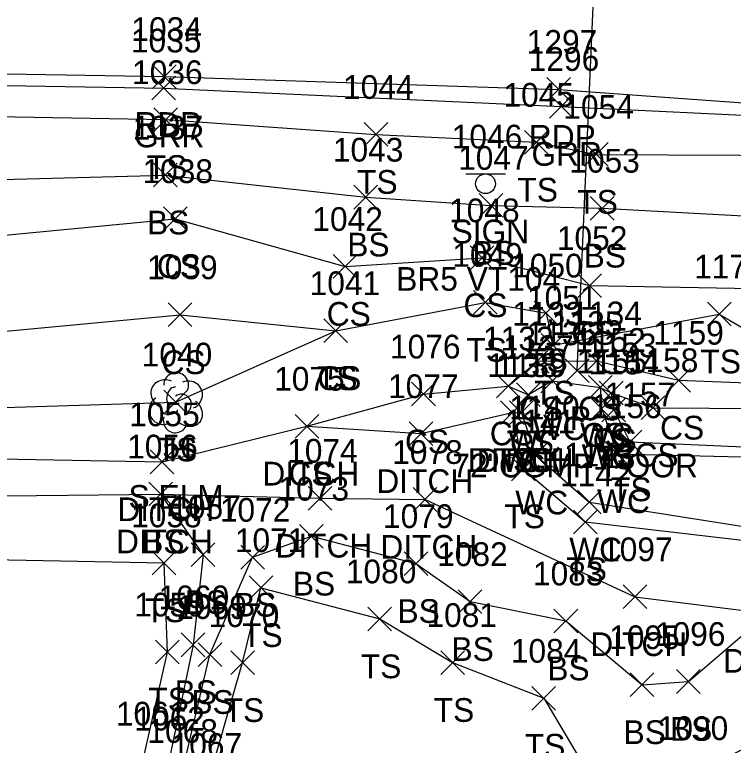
# Model space of a CAD drawing. Extents: x 1514253 to 1516033, y 782541 to 785002.
# Drawn here: x 1515259.8 to 1515320.5, y 782627.7 to 782689.3 of the extents above; entities that cross this region are included whole.
import ezdxf

# ---------------------------------------------------------------- set-up
doc = ezdxf.new("R2010")
doc.units = 0
for name, color, linetype in [('D_A', 7, 'Continuous'), ('D_C', 7, 'Continuous'), ('D_I', 7, 'Continuous'), ('D_TIC', 7, 'Continuous'), ('DCP', 7, 'Continuous'), ('DD', 7, 'Continuous'), ('L_A', 7, 'Continuous'), ('L_C', 7, 'Continuous'), ('L_I', 7, 'Continuous'), ('L_TIC', 7, 'Continuous'), ('LAWE', 7, 'Continuous'), ('LELB', 7, 'Continuous'), ('LTD', 7, 'Continuous'), ('P_A', 7, 'Continuous'), ('P_I', 7, 'Continuous'), ('P_TIC', 7, 'Continuous'), ('PET', 7, 'Continuous'), ('R_A', 7, 'Continuous'), ('R_I', 7, 'Continuous'), ('R_TIC', 7, 'Continuous'), ('RGR', 7, 'Continuous'), ('S_A', 7, 'Continuous'), ('S_C', 7, 'Continuous'), ('S_I', 7, 'Continuous'), ('SSGN', 7, 'Continuous')]:
    doc.layers.add(name, color=color, linetype=linetype)

msp = doc.modelspace()

# ---------------------------------------------------------------- linework, layer by layer
at = {"layer": 'D_TIC'}
for points in [[(1515306.297, 782658.246), (1515308.297, 782660.246)], [(1515308.297, 782658.246), (1515306.297, 782660.246)], [(1515300.839, 782654.709), (1515302.839, 782656.709)], [(1515302.839, 782654.709), (1515300.839, 782656.709)], [(1515301.59, 782654.701), (1515303.59, 782656.701)], [(1515303.59, 782654.701), (1515301.59, 782656.701)], [(1515283.508, 782653.562), (1515285.508, 782655.562)], [(1515285.508, 782653.562), (1515283.508, 782655.562)], [(1515293.121, 782652.933), (1515295.121, 782654.933)], [(1515295.121, 782652.933), (1515293.121, 782654.933)], [(1515271.278, 782650.56), (1515273.278, 782652.56)], [(1515273.278, 782650.56), (1515271.278, 782652.56)], [(1515271.163, 782647.844), (1515273.163, 782649.844)], [(1515273.163, 782647.844), (1515271.163, 782649.844)], [(1515284.608, 782647.488), (1515286.608, 782649.488)], [(1515286.608, 782647.488), (1515284.608, 782649.488)], [(1515293.464, 782647.384), (1515295.464, 782649.384)], [(1515295.464, 782647.384), (1515293.464, 782649.384)], [(1515311.17, 782639.182), (1515313.17, 782641.182)], [(1515313.17, 782639.182), (1515311.17, 782641.182)]]:
    msp.add_lwpolyline(points, dxfattribs=at)
at = {"layer": 'DCP'}
msp.add_lwpolyline([(1515307.297, 782659.246), (1515310.82, 782739.152)], dxfattribs=at)
at = {"layer": 'DD'}
for points in [[(1515199.546, 782651.884), (1515235.764, 782652.236), (1515272.278, 782651.56), (1515284.508, 782654.562), (1515294.121, 782653.933), (1515301.839, 782655.709), (1515302.59, 782655.701)], [(1515199.394, 782648.84), (1515235.483, 782648.45), (1515272.163, 782648.844), (1515285.608, 782648.488), (1515294.464, 782648.384), (1515312.17, 782640.182), (1515323.367, 782638.781), (1515329.306, 782640.309), (1515333.451, 782637.848), (1515333.036, 782633.949), (1515334.721, 782622.814), (1515328.394, 782601.12)]]:
    msp.add_lwpolyline(points, dxfattribs=at)
at = {"layer": 'L_TIC'}
for points in [[(1515271.581, 782679.406), (1515273.581, 782681.406)], [(1515273.581, 782679.406), (1515271.581, 782681.406)], [(1515289.322, 782678.158), (1515291.322, 782680.158)], [(1515291.322, 782678.158), (1515289.322, 782680.158)], [(1515302.85, 782677.499), (1515304.85, 782679.499)], [(1515304.85, 782677.499), (1515302.85, 782679.499)], [(1515307.9, 782676.477), (1515309.9, 782678.477)], [(1515309.9, 782676.477), (1515307.9, 782678.477)], [(1515271.569, 782674.732), (1515273.569, 782676.732)], [(1515273.569, 782674.732), (1515271.569, 782676.732)], [(1515288.461, 782672.873), (1515290.461, 782674.873)], [(1515290.461, 782672.873), (1515288.461, 782674.873)], [(1515299.027, 782672.178), (1515301.027, 782674.178)], [(1515301.027, 782672.178), (1515299.027, 782674.178)], [(1515308.403, 782671.939), (1515310.403, 782673.939)], [(1515310.403, 782671.939), (1515308.403, 782673.939)], [(1515272.401, 782671.059), (1515274.401, 782673.059)], [(1515274.401, 782671.059), (1515272.401, 782673.059)], [(1515298.264, 782667.757), (1515300.264, 782669.757)], [(1515300.264, 782667.757), (1515298.264, 782669.757)], [(1515286.729, 782667.029), (1515288.729, 782669.029)], [(1515288.729, 782667.029), (1515286.729, 782669.029)], [(1515307.354, 782665.42), (1515309.354, 782667.42)], [(1515309.354, 782665.42), (1515307.354, 782667.42)], [(1515298.54, 782664.004), (1515300.54, 782666.004)], [(1515300.54, 782664.004), (1515298.54, 782666.004)], [(1515272.8, 782662.957), (1515274.8, 782664.957)], [(1515274.8, 782662.957), (1515272.8, 782664.957)], [(1515303.675, 782663.101), (1515305.675, 782665.101)], [(1515305.675, 782663.101), (1515303.675, 782665.101)], [(1515318.285, 782663.015), (1515320.285, 782665.015)], [(1515320.285, 782663.015), (1515318.285, 782665.015)], [(1515285.933, 782661.615), (1515287.933, 782663.615)], [(1515287.933, 782661.615), (1515285.933, 782663.615)], [(1515285.933, 782661.615), (1515287.933, 782663.615)], [(1515287.933, 782661.615), (1515285.933, 782663.615)], [(1515304.267, 782660.39), (1515306.267, 782662.39)], [(1515306.267, 782660.39), (1515304.267, 782662.39)], [(1515302.943, 782659.043), (1515304.943, 782661.043)], [(1515304.943, 782659.043), (1515302.943, 782661.043)], [(1515307.932, 782659.064), (1515309.932, 782661.064)], [(1515309.932, 782659.064), (1515307.932, 782661.064)], [(1515304.221, 782657.389), (1515306.221, 782659.389)], [(1515306.221, 782657.389), (1515304.221, 782659.389)], [(1515304.221, 782657.389), (1515306.221, 782659.389)], [(1515306.221, 782657.389), (1515304.221, 782659.389)], [(1515314.851, 782657.437), (1515316.851, 782659.437)], [(1515316.851, 782657.437), (1515314.851, 782659.437)], [(1515300.485, 782656.951), (1515302.485, 782658.951)], [(1515302.485, 782656.951), (1515300.485, 782658.951)], [(1515300.485, 782656.951), (1515302.485, 782658.951)], [(1515302.485, 782656.951), (1515300.485, 782658.951)], [(1515308.247, 782656.829), (1515310.247, 782658.829)], [(1515310.247, 782656.829), (1515308.247, 782658.829)], [(1515308.247, 782656.829), (1515310.247, 782658.829)], [(1515310.247, 782656.829), (1515308.247, 782658.829)], [(1515293.334, 782656.273), (1515295.334, 782658.273)], [(1515295.334, 782656.273), (1515293.334, 782658.273)], [(1515302.181, 782656.217), (1515304.181, 782658.217)], [(1515304.181, 782656.217), (1515302.181, 782658.217)], [(1515302.181, 782656.217), (1515304.181, 782658.217)], [(1515304.181, 782656.217), (1515302.181, 782658.217)], [(1515309.163, 782656.372), (1515311.163, 782658.372)], [(1515311.163, 782656.372), (1515309.163, 782658.372)], [(1515309.163, 782656.372), (1515311.163, 782658.372)], [(1515311.163, 782656.372), (1515309.163, 782658.372)], [(1515272.423, 782655.598), (1515274.423, 782657.598)], [(1515274.423, 782655.598), (1515272.423, 782657.598)], [(1515300.839, 782654.709), (1515302.839, 782656.709)], [(1515302.839, 782654.709), (1515300.839, 782656.709)], [(1515308.37, 782655.024), (1515310.37, 782657.024)], [(1515310.37, 782655.024), (1515308.37, 782657.024)], [(1515309.383, 782654.934), (1515311.383, 782656.934)], [(1515311.383, 782654.934), (1515309.383, 782656.934)], [(1515312.696, 782655.121), (1515314.696, 782657.121)], [(1515314.696, 782655.121), (1515312.696, 782657.121)], [(1515301.59, 782654.701), (1515303.59, 782656.701)], [(1515303.59, 782654.701), (1515301.59, 782656.701)], [(1515283.508, 782653.562), (1515285.508, 782655.562)], [(1515285.508, 782653.562), (1515283.508, 782655.562)], [(1515310.738, 782652.239), (1515312.738, 782654.239)], [(1515312.738, 782652.239), (1515310.738, 782654.239)], [(1515302.77, 782651.127), (1515304.77, 782653.127)], [(1515304.77, 782651.127), (1515302.77, 782653.127)], [(1515309.661, 782651.237), (1515311.661, 782653.237)], [(1515311.661, 782651.237), (1515309.661, 782653.237)], [(1515301.751, 782649.961), (1515303.751, 782651.961)], [(1515303.751, 782649.961), (1515301.751, 782651.961)], [(1515271.163, 782647.844), (1515273.163, 782649.844)], [(1515273.163, 782647.844), (1515271.163, 782649.844)], [(1515307.32, 782647.165), (1515309.32, 782649.165)], [(1515309.32, 782647.165), (1515307.32, 782649.165)], [(1515306.982, 782645.496), (1515308.982, 782647.496)], [(1515308.982, 782645.496), (1515306.982, 782647.496)], [(1515283.876, 782644.286), (1515285.876, 782646.286)], [(1515285.876, 782644.286), (1515283.876, 782646.286)], [(1515274.745, 782642.731), (1515276.745, 782644.731)], [(1515276.745, 782642.731), (1515274.745, 782644.731)], [(1515278.925, 782642.508), (1515280.925, 782644.508)], [(1515280.925, 782642.508), (1515278.925, 782644.508)], [(1515271.442, 782642.038), (1515273.442, 782644.038)], [(1515273.442, 782642.038), (1515271.442, 782644.038)], [(1515292.699, 782641.978), (1515294.699, 782643.978)], [(1515294.699, 782641.978), (1515292.699, 782643.978)], [(1515279.627, 782639.948), (1515281.627, 782641.948)], [(1515281.627, 782639.948), (1515279.627, 782641.948)], [(1515297.257, 782638.773), (1515299.257, 782640.773)], [(1515299.257, 782638.773), (1515297.257, 782640.773)], [(1515289.641, 782637.315), (1515291.641, 782639.315)], [(1515291.641, 782637.315), (1515289.641, 782639.315)], [(1515305.339, 782637.14), (1515307.339, 782639.14)], [(1515307.339, 782637.14), (1515305.339, 782639.14)], [(1515273.9, 782635.131), (1515275.9, 782637.131)], [(1515275.9, 782635.131), (1515273.9, 782637.131)], [(1515271.72, 782634.52), (1515273.72, 782636.52)], [(1515273.72, 782634.52), (1515271.72, 782636.52)], [(1515275.319, 782634.308), (1515277.319, 782636.308)], [(1515277.319, 782634.308), (1515275.319, 782636.308)], [(1515278.076, 782633.626), (1515280.076, 782635.626)], [(1515280.076, 782633.626), (1515278.076, 782635.626)], [(1515295.789, 782633.635), (1515297.789, 782635.635)], [(1515297.789, 782633.635), (1515295.789, 782635.635)], [(1515315.681, 782632.039), (1515317.681, 782634.039)], [(1515317.681, 782632.039), (1515315.681, 782634.039)], [(1515311.767, 782631.766), (1515313.767, 782633.766)], [(1515313.767, 782631.766), (1515311.767, 782633.766)], [(1515303.473, 782630.621), (1515305.473, 782632.621)], [(1515305.473, 782630.621), (1515303.473, 782632.621)]]:
    msp.add_lwpolyline(points, dxfattribs=at)
at = {"layer": 'LAWE'}
for points in [[(1515305.221, 782658.389), (1515303.181, 782657.217), (1515302.59, 782655.701), (1515303.77, 782652.127), (1515308.32, 782648.165), (1515322.585, 782645.92), (1515334.724, 782645.203), (1515346.696, 782645.723), (1515355.669, 782642.743), (1515362.112, 782639.578)], [(1515305.221, 782658.389), (1515309.247, 782657.829), (1515309.37, 782656.024), (1515310.661, 782652.237), (1515328.158, 782651.8), (1515339.372, 782649.611), (1515359.133, 782646.008), (1515370.291, 782640.974), (1515378.24, 782634.81), (1515385.256, 782635.895), (1515388.599, 782640.179), (1515389.121, 782646.36), (1515386.777, 782649.906), (1515390.568, 782651.945), (1515397.927, 782652.705), (1515407.459, 782649.219), (1515414.933, 782648.068), (1515419.945, 782646.777), (1515424.071, 782644.52), (1515427.947, 782638.847), (1515430.432, 782625.437), (1515426.178, 782619.034), (1515431.378, 782612.516)]]:
    msp.add_lwpolyline(points, dxfattribs=at)
at = {"layer": 'LELB'}
for points in [[(1515198.723, 782678.684), (1515237.654, 782681.037), (1515272.581, 782680.406), (1515290.322, 782679.158), (1515303.85, 782678.499), (1515308.9, 782677.477), (1515327.05, 782677.392), (1515347.388, 782677.23), (1515355.314, 782675.991), (1515384.856, 782670.273), (1515402.641, 782668.137), (1515426.898, 782664.758), (1515431.084, 782662.879), (1515448.442, 782660.296)], [(1515199.146, 782675.609), (1515237.424, 782674.791), (1515272.569, 782675.732), (1515289.461, 782673.873), (1515300.027, 782673.178), (1515309.403, 782672.939), (1515327.016, 782671.989), (1515352.175, 782674.367), (1515355.484, 782668.368), (1515355.529, 782661.896), (1515362.199, 782656.243), (1515384.653, 782653.272), (1515398.956, 782656.377), (1515406.884, 782653.846), (1515416.301, 782653.121), (1515424.335, 782655.884), (1515430.378, 782659.607), (1515449.299, 782656.525)], [(1515199.979, 782655.093), (1515236.324, 782655.449), (1515273.423, 782656.598), (1515286.933, 782662.615), (1515299.54, 782665.004), (1515304.675, 782664.101), (1515305.267, 782661.39), (1515319.285, 782664.015), (1515324.873, 782660.753), (1515330.533, 782661.03), (1515335.531, 782663.335), (1515351.626, 782666.228), (1515352.175, 782674.367)], [(1515199.887, 782668.087), (1515237.312, 782668.583), (1515273.401, 782672.059), (1515287.729, 782668.029), (1515299.264, 782668.757), (1515308.354, 782666.42), (1515328.224, 782666.061), (1515330.533, 782661.03), (1515333.755, 782659.052), (1515343.884, 782659.192), (1515351.413, 782658.187), (1515355.484, 782668.368), (1515366.848, 782667.84), (1515384.002, 782666.142), (1515400.676, 782664.245), (1515424.648, 782661.721), (1515431.013, 782661.432), (1515448.86, 782658.438)], [(1515199.251, 782662.64), (1515236.544, 782660.479), (1515273.8, 782663.957), (1515286.933, 782662.615)], [(1515284.508, 782654.562), (1515294.334, 782657.273), (1515301.485, 782657.951), (1515303.943, 782660.043), (1515308.932, 782660.064), (1515315.851, 782658.437), (1515327.358, 782657.995), (1515341.712, 782655.566), (1515348.371, 782655.012), (1515351.413, 782658.187), (1515355.529, 782661.896), (1515364.984, 782660.684), (1515382.517, 782659.229), (1515399.983, 782660.3), (1515424.268, 782658.95)], [(1515301.485, 782657.951), (1515303.181, 782657.217)], [(1515309.247, 782657.829), (1515310.163, 782657.372), (1515313.696, 782656.121), (1515327.927, 782656.035), (1515341.024, 782653.35), (1515349.767, 782652.941), (1515361.602, 782650.791), (1515374.165, 782648.283), (1515380.971, 782647.67), (1515386.077, 782649.544)], [(1515310.163, 782657.372), (1515310.383, 782655.934), (1515311.738, 782653.239), (1515327.12, 782652.556), (1515340.38, 782650.599), (1515359.526, 782647.53), (1515371.713, 782643.995), (1515378.608, 782636.912), (1515384.051, 782637.622), (1515387.007, 782640.366), (1515387.011, 782646.011), (1515386.077, 782649.544), (1515388.534, 782653.757), (1515398.392, 782653.907), (1515407.552, 782650.359), (1515415.675, 782649.762), (1515419.247, 782648.751), (1515425.267, 782646.15), (1515433.214, 782625.745), (1515427.667, 782618.999), (1515432.728, 782613.436)], [(1515301.839, 782655.709), (1515302.751, 782650.961), (1515307.982, 782646.496), (1515322.678, 782644.788), (1515335.13, 782644.312), (1515345.143, 782643.295), (1515351.972, 782643.192)], [(1515272.163, 782648.844), (1515275.745, 782643.731), (1515274.9, 782636.131), (1515272.765, 782625.903), (1515266.399, 782619.826)], [(1515198.67, 782646.535), (1515234.653, 782643.768), (1515272.442, 782643.038), (1515272.72, 782635.52), (1515270.641, 782626.326), (1515264.311, 782620.96)], [(1515267.096, 782619.076), (1515273.864, 782624.863), (1515276.319, 782635.308), (1515279.925, 782643.508), (1515284.876, 782645.286), (1515293.699, 782642.978), (1515298.257, 782639.773), (1515306.339, 782638.14), (1515312.767, 782632.766), (1515316.681, 782633.039), (1515323.367, 782638.781), (1515328.746, 782636.685), (1515333.036, 782633.949)], [(1515267.493, 782617.708), (1515275.905, 782623.682), (1515279.076, 782634.626), (1515280.627, 782640.948), (1515290.641, 782638.315), (1515296.789, 782634.635), (1515304.473, 782631.621), (1515309.893, 782622.536), (1515316.95, 782625.103), (1515323.664, 782628.572), (1515323.948, 782631.832), (1515325.669, 782634.817), (1515329.658, 782632.505), (1515330.558, 782622.703), (1515325.128, 782602.902)]]:
    msp.add_lwpolyline(points, dxfattribs=at)
at = {"layer": 'LTD'}
msp.add_line((1515273.423, 782656.598), (1515273.423, 782656.598), dxfattribs=at)
msp.add_line((1515273.423, 782656.598), (1515273.423, 782656.598), dxfattribs=at)
msp.add_arc((1515273.47, 782658.032), 1.047, 335.52715, 180.95627, dxfattribs=at)
for centre, major_axis, ratio, start_param, end_param in [((1515272.631, 782657.264), (1.21, -0.512), 0.895232, 1.570796, 4.712389), ((1515274.465, 782657.181), (-1.141, -0.483), 0.949671, 1.570796, 4.712389), ((1515273.215, 782657.056), (-0.208, -0.792), 0.645439, 3.141593, 6.283185), ((1515273.923, 782656.431), (-0.5, 0.667), 0.989748, 3.141593, 6.283185), ((1515272.34, 782655.889), (0.584, -1.042), 0.959034, 3.141593, 6.283185), ((1515274.423, 782655.764), (-1.09, 0.792), 0.841452, 1.570796, 4.712389), ((1515272.965, 782655.847), (-0.625, -0.083), 0.423636, 0, 3.141593), ((1515273.423, 782655.098), (0.265, 1.061), 0.942809, 1.570796, 4.712389)]:
    msp.add_ellipse(centre, major_axis=major_axis, ratio=ratio, start_param=start_param, end_param=end_param, dxfattribs=at)
at = {"layer": 'P_TIC'}
for points in [[(1515271.463, 782683.04), (1515273.463, 782685.04)], [(1515273.463, 782683.04), (1515271.463, 782685.04)], [(1515304.734, 782681.962), (1515306.734, 782683.962)], [(1515306.734, 782681.962), (1515304.734, 782683.962)]]:
    msp.add_lwpolyline(points, dxfattribs=at)
at = {"layer": 'PET'}
msp.add_lwpolyline([(1515199.633, 782684.061), (1515237.525, 782684.632), (1515272.463, 782684.04), (1515305.734, 782682.962), (1515349.744, 782679.786), (1515389.071, 782675.303), (1515418.681, 782671.113), (1515450.732, 782666.149)], dxfattribs=at)
at = {"layer": 'R_TIC'}
for points in [[(1515271.426, 782682.075), (1515273.426, 782684.075)], [(1515273.426, 782682.075), (1515271.426, 782684.075)], [(1515304.957, 782680.521), (1515306.957, 782682.521)], [(1515306.957, 782680.521), (1515304.957, 782682.521)]]:
    msp.add_lwpolyline(points, dxfattribs=at)
at = {"layer": 'RGR'}
msp.add_lwpolyline([(1515199.059, 782680.993), (1515237.496, 782683.643), (1515272.426, 782683.075), (1515305.957, 782681.521), (1515350.167, 782679.409), (1515389.004, 782674.461), (1515418.688, 782670.319), (1515449.265, 782662.37)], dxfattribs=at)
at = {"layer": 'SSGN'}
for p, q in [((1515297.919, 782675.834), (1515301.252, 782675.834)), ((1515299.566, 782675), (1515299.566, 782675))]:
    msp.add_line(p, q, dxfattribs=at)
msp.add_circle((1515299.566, 782675), 0.833, dxfattribs=at)

# ---------------------------------------------------------------- texts
at = {"layer": 'D_A'}
for s, p in [('P', (1515306.675, 782654.246)), ('DITCH', (1515298.075, 782650.709)), ('DITCH', (1515298.826, 782650.701)), ('DITCH', (1515280.744, 782649.562)), ('DITCH', (1515290.357, 782648.933)), ('DITCH', (1515268.514, 782646.56)), ('DITCH', (1515268.399, 782643.844)), ('DITCH', (1515281.844, 782643.488)), ('DITCH', (1515290.7, 782643.384)), ('DITCH', (1515308.406, 782635.182)), ('DITCH', (1515319.603, 782633.781))]:
    msp.add_text(s, height=2, dxfattribs=at).set_placement(p)
at = {"layer": 'D_C'}
msp.add_text('72"CGMP-POOR', height=2, dxfattribs=at).set_placement((1515296.77, 782650.246))
at = {"layer": 'D_I'}
for s, p in [('1135', (1515305.171, 782662.246)), ('1138', (1515299.713, 782658.709)), ('1139', (1515300.456, 782658.701)), ('1075', (1515281.736, 782657.562)), ('1077', (1515291.349, 782656.933)), ('1055', (1515269.507, 782654.56)), ('1056', (1515269.336, 782651.844)), ('1074', (1515282.836, 782651.488)), ('1078', (1515291.692, 782651.384)), ('1097', (1515309.398, 782643.182))]:
    msp.add_text(s, height=2, dxfattribs=at).set_placement(p)
at = {"layer": 'L_A'}
for s, p in [('TS', (1515270.991, 782675.406)), ('TS', (1515288.731, 782674.158)), ('TS', (1515302.259, 782673.499)), ('TS', (1515307.31, 782672.477)), ('BS', (1515271.01, 782670.732)), ('BS', (1515287.902, 782668.873)), ('BS', (1515298.468, 782668.178)), ('BS', (1515307.844, 782667.939)), ('CS', (1515271.842, 782667.059)), ('CS', (1515297.705, 782663.757)), ('CS', (1515286.17, 782663.029)), ('CS', (1515306.795, 782661.42)), ('TS', (1515297.95, 782660.004)), ('TS', (1515303.084, 782659.101)), ('TS', (1515317.694, 782659.015)), ('CS', (1515272.241, 782658.957)), ('TS', (1515285.343, 782657.615)), ('CS', (1515285.374, 782657.615)), ('TS', (1515303.676, 782656.39)), ('CS', (1515302.384, 782655.043)), ('CS', (1515307.373, 782655.064)), ('CS', (1515299.926, 782652.951)), ('CS', (1515299.926, 782652.951)), ('WC', (1515303.528, 782653.389)), ('WC', (1515303.528, 782653.389)), ('WC', (1515307.554, 782652.829)), ('CS', (1515307.688, 782652.829)), ('CS', (1515314.291, 782653.437)), ('CS', (1515292.775, 782652.273)), ('WC', (1515301.489, 782652.217)), ('CS', (1515301.622, 782652.217)), ('TS', (1515308.572, 782652.372)), ('CS', (1515308.604, 782652.372)), ('TS', (1515271.833, 782651.598)), ('H', (1515272.856, 782651.598)), ('WC', (1515307.678, 782651.024)), ('CS', (1515312.136, 782651.121)), ('TS', (1515300.249, 782650.709)), ('WC', (1515300.897, 782650.701)), ('TS', (1515308.792, 782650.934)), ('CS', (1515282.949, 782649.562)), ('TS', (1515310.148, 782648.239)), ('WC', (1515302.077, 782647.127)), ('WC', (1515308.969, 782647.237)), ('TS', (1515301.16, 782645.961)), ('BS', (1515270.604, 782643.844)), ('WC', (1515306.627, 782643.165)), ('TS', (1515306.392, 782641.496)), ('BS', (1515283.317, 782640.286)), ('BS', (1515274.186, 782638.731)), ('BS', (1515278.366, 782638.508)), ('TS', (1515270.852, 782638.038)), ('BS', (1515292.14, 782637.978)), ('TS', (1515279.036, 782635.948)), ('BS', (1515296.698, 782634.773)), ('TS', (1515289.05, 782633.315)), ('BS', (1515304.78, 782633.14)), ('BS', (1515273.34, 782631.131)), ('TS', (1515271.129, 782630.52)), ('BS', (1515274.76, 782630.308)), ('TS', (1515277.485, 782629.626)), ('TS', (1515295.198, 782629.635)), ('BS', (1515311.208, 782627.766)), ('BS', (1515315.122, 782628.039)), ('TS', (1515302.883, 782626.621))]:
    msp.add_text(s, height=2, dxfattribs=at).set_placement(p)
at = {"layer": 'L_C'}
msp.add_text('S.ELM', height=2, dxfattribs=at).set_placement((1515269.455, 782647.598))
at = {"layer": 'L_I'}
for s, p in [('1036', (1515269.754, 782683.406)), ('1044', (1515287.55, 782682.158)), ('1045', (1515301.078, 782681.499)), ('1054', (1515306.128, 782680.477)), ('1037', (1515269.797, 782678.732)), ('1043', (1515286.689, 782676.873)), ('1047', (1515297.255, 782676.178)), ('1053', (1515306.631, 782675.939)), ('1038', (1515270.63, 782675.059)), ('1048', (1515296.493, 782671.757)), ('1042', (1515284.957, 782671.029)), ('1052', (1515305.582, 782669.42)), ('1049', (1515296.761, 782668.004)), ('1050', (1515301.816, 782667.101)), ('1173', (1515317.159, 782667.015)), ('1039', (1515271.02, 782666.957)), ('1041', (1515284.729, 782665.615)), ('1041', (1515284.729, 782665.615)), ('1051', (1515303.062, 782664.39)), ('1133', (1515301.817, 782663.043)), ('1134', (1515306.806, 782663.064)), ('1132', (1515299.359, 782660.951)), ('1132', (1515299.359, 782660.951)), ('1136', (1515303.04, 782661.389)), ('1136', (1515303.04, 782661.389)), ('1159', (1515313.717, 782661.437)), ('1076', (1515291.508, 782660.273)), ('1152', (1515307.121, 782660.829)), ('1152', (1515307.121, 782660.829)), ('1153', (1515308.037, 782660.372)), ('1153', (1515308.037, 782660.372)), ('1137', (1515301.055, 782660.217)), ('1137', (1515301.055, 782660.217)), ('1040', (1515270.565, 782659.598)), ('1040', (1515270.565, 782659.598)), ('1155', (1515307.244, 782659.024)), ('1158', (1515311.57, 782659.121)), ('1138', (1515299.713, 782658.709)), ('1139', (1515300.456, 782658.701)), ('1154', (1515308.257, 782658.934)), ('1075', (1515281.736, 782657.562)), ('1157', (1515309.612, 782656.239)), ('1140', (1515301.557, 782655.127)), ('1156', (1515308.48, 782655.237)), ('1141', (1515301.192, 782653.961)), ('1056', (1515269.336, 782651.844)), ('1143', (1515306.194, 782651.165)), ('1142', (1515305.856, 782649.496)), ('1073', (1515282.104, 782648.286)), ('1057', (1515272.974, 782646.731)), ('1072', (1515277.153, 782646.508)), ('1058', (1515269.671, 782646.038)), ('1079', (1515290.919, 782645.978)), ('1071', (1515278.422, 782643.948)), ('1082', (1515295.485, 782642.773)), ('1080', (1515287.783, 782641.315)), ('1083', (1515303.567, 782641.14)), ('1060', (1515271.994, 782639.131)), ('1059', (1515269.94, 782638.52)), ('1069', (1515273.492, 782638.308)), ('1070', (1515276.218, 782637.626)), ('1081', (1515294.584, 782637.635)), ('1095', (1515309.995, 782635.766)), ('1096', (1515313.854, 782636.039)), ('1084', (1515301.702, 782634.621)), ('1061', (1515268.389, 782629.326)), ('1062', (1515269.947, 782628.903)), ('1068', (1515271.045, 782627.863)), ('1090', (1515314.092, 782628.103)), ('1067', (1515273.086, 782626.682))]:
    msp.add_text(s, height=2, dxfattribs=at).set_placement(p)
at = {"layer": 'P_A'}
for p in [(1515269.951, 782679.04), (1515303.222, 782677.962)]:
    msp.add_text('RDP', height=2, dxfattribs=at).set_placement(p)
at = {"layer": 'P_I'}
for s, p in [('1034', (1515269.691, 782687.04)), ('1297', (1515303.041, 782685.962))]:
    msp.add_text(s, height=2, dxfattribs=at).set_placement(p)
at = {"layer": 'R_A'}
for p in [(1515269.914, 782678.075), (1515303.445, 782676.521)]:
    msp.add_text('GRR', height=2, dxfattribs=at).set_placement(p)
at = {"layer": 'R_I'}
for s, p in [('1035', (1515269.654, 782686.075)), ('1296', (1515303.209, 782684.521))]:
    msp.add_text(s, height=2, dxfattribs=at).set_placement(p)
at = {"layer": 'S_A'}
msp.add_text('SIGN', height=2, dxfattribs=at).set_placement((1515296.704, 782669.98))
at = {"layer": 'S_C'}
msp.add_text('BR5 VT104', height=2, dxfattribs=at).set_placement((1515292.034, 782665.98))
at = {"layer": 'S_I'}
msp.add_text('1046', height=2, dxfattribs=at).set_placement((1515296.719, 782677.98))

doc.saveas('drawing.dxf')
